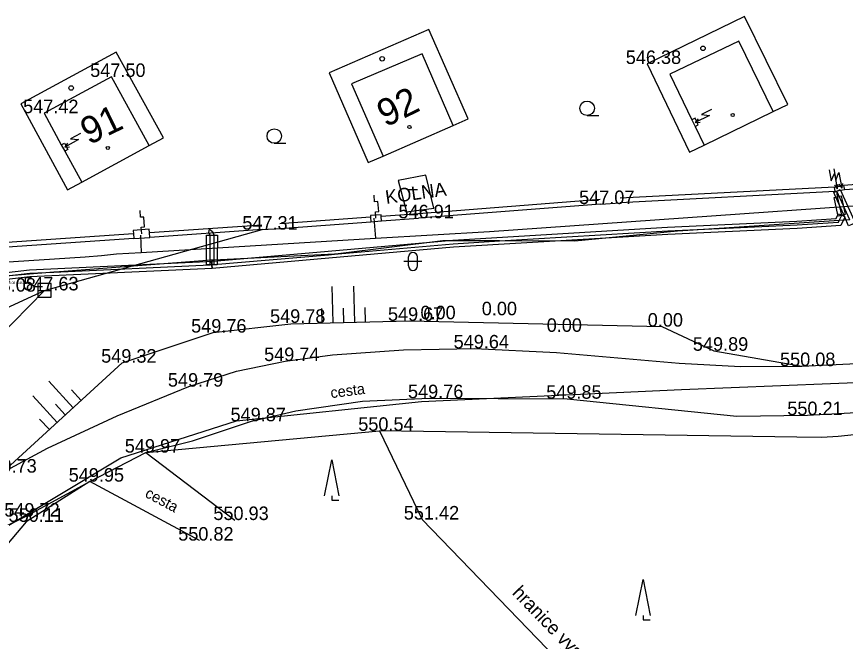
# Model space of a CAD drawing. Extents: x -669995 to -669686, y -1125551 to -1125263.
# Drawn here: x -669816.2 to -669770.25, y -1125420.77 to -1125386.11 of the extents above; entities that cross this region are included whole.
import ezdxf

# ---------------------------------------------------------------- set-up
doc = ezdxf.new("R2010")
doc.units = 0
for name, color, linetype in [('G_Bod_tecka', 7, 'Continuous'), ('G_Bod_vyska', 7, 'Continuous'), ('G_Breh_Teren', 7, 'Continuous'), ('G_Budovy-znacky', 7, 'Continuous'), ('G_Budovy_Objekty', 7, 'Continuous'), ('G_Cesty_Schody', 7, 'Continuous'), ('G_Cisla_orientacni', 7, 'Continuous'), ('G_Ploty', 7, 'Continuous'), ('G_Ploty_vstupy', 7, 'Continuous'), ('G_Popisy_objektu', 7, 'Continuous'), ('G_Popisy_povrchu', 7, 'Continuous'), ('G_Poznamky_odkaz', 7, 'Continuous'), ('G_Site-kanalizace', 7, 'Continuous'), ('G_Site-Rozvadece', 7, 'Continuous'), ('G_Vyskove_srafy', 7, 'Continuous'), ('G_Z_CHRANICKA-TEPLOVOD_kotovane', 7, 'Continuous'), ('G_Z_ELsilove_podz_kotovane', 7, 'Continuous'), ('G_Z_ELsilove_zrusene', 7, 'Continuous'), ('G_Z_PLYNY_podz_geodeticky', 7, 'Continuous'), ('G_Zelen-okraj', 7, 'Continuous'), ('G_Zelen-Znacky', 7, 'Continuous'), ('Vrstva 2', 7, 'Continuous')]:
    doc.layers.add(name, color=color, linetype=linetype)

msp = doc.modelspace()

# ---------------------------------------------------------------- linework, layer by layer
at = {"layer": 'G_Bod_tecka'}
for p, q in [((-669781.25, -1125388.74), (-669781.25, -1125388.74)), ((-669810.93, -1125389.46), (-669810.93, -1125389.46)), ((-669814.67, -1125391.47), (-669814.67, -1125391.47)), ((-669783.83, -1125396.51), (-669783.83, -1125396.51)), ((-669793.91, -1125397.3), (-669793.91, -1125397.3)), ((-669802.58, -1125397.93), (-669802.58, -1125397.93)), ((-669814.65, -1125401.3), (-669814.65, -1125401.3)), ((-669789.63, -1125402.68), (-669789.63, -1125402.68)), ((-669800.99, -1125403.1), (-669800.99, -1125403.1)), ((-669794.43, -1125402.99), (-669794.43, -1125402.99)), ((-669793.03, -1125402.9), (-669793.03, -1125402.9)), ((-669805.34, -1125403.64), (-669805.34, -1125403.64)), ((-669786.03, -1125403.6), (-669786.03, -1125403.6)), ((-669780.43, -1125403.31), (-669780.43, -1125403.31)), ((-669790.8, -1125404.52), (-669790.8, -1125404.52)), ((-669777.54, -1125404.65), (-669777.54, -1125404.65)), ((-669810.34, -1125405.31), (-669810.34, -1125405.31)), ((-669801.31, -1125405.22), (-669801.31, -1125405.22)), ((-669772.67, -1125405.5), (-669772.67, -1125405.5)), ((-669806.64, -1125406.64), (-669806.64, -1125406.64)), ((-669793.32, -1125407.28), (-669793.32, -1125407.28)), ((-669785.67, -1125407.31), (-669785.67, -1125407.31)), ((-669772.35, -1125408.22), (-669772.35, -1125408.22)), ((-669803.17, -1125408.56), (-669803.17, -1125408.56)), ((-669796.07, -1125409.09), (-669796.07, -1125409.09)), ((-669809.03, -1125410.3), (-669809.03, -1125410.3)), ((-669812.14, -1125411.91), (-669812.14, -1125411.91)), ((-669815.71, -1125413.85), (-669815.71, -1125413.85)), ((-669815.66, -1125414.14), (-669815.66, -1125414.14)), ((-669804.1, -1125414.04), (-669804.1, -1125414.04)), ((-669793.71, -1125414.01), (-669793.71, -1125414.01)), ((-669806.05, -1125415.18), (-669806.05, -1125415.18))]:
    msp.add_line(p, q, dxfattribs=at)
at = {"layer": 'G_Breh_Teren'}
for p, q in [((-669814.65, -1125401.3), (-669802.58, -1125397.93)), ((-669814.65, -1125401.3), (-669821.82, -1125408.62)), ((-669805.29, -1125403.64), (-669800.99, -1125403.15)), ((-669800.99, -1125403.15), (-669794.43, -1125402.99)), ((-669794.43, -1125402.99), (-669780.43, -1125403.31)), ((-669810.34, -1125405.31), (-669805.29, -1125403.64)), ((-669816.98, -1125411.41), (-669810.34, -1125405.31)), ((-669809.03, -1125410.3), (-669796.07, -1125409.09)), ((-669812.14, -1125411.91), (-669815.66, -1125414.14)), ((-669815.66, -1125414.14), (-669820.77, -1125420.13))]:
    msp.add_line(p, q, dxfattribs=at)
for points in [[(-669780.43, -1125403.31), (-669777.54, -1125404.65), (-669772.67, -1125405.5)], [(-669769.42, -1125409.28), (-669770.65, -1125409.41), (-669771.56, -1125409.46), (-669772.94, -1125409.45), (-669796.07, -1125409.09)]]:
    msp.add_lwpolyline(points, dxfattribs=at)
at = {"layer": 'G_Budovy-znacky'}
msp.add_line((-669794.47, -1125395.71), (-669793.97, -1125395.71), dxfattribs=at)
for centre, radius in [((-669778.15, -1125387.87), 0.125), ((-669795.93, -1125388.45), 0.125), ((-669813.17, -1125390.07), 0.125), ((-669776.499, -1125391.57), 0.0875), ((-669794.42, -1125392.24), 0.0875), ((-669811.14, -1125393.399), 0.0875)]:
    msp.add_circle(centre, radius, dxfattribs=at)
at = {"layer": 'G_Budovy_Objekty'}
for p, q in [((-669775.84, -1125386.11), (-669781.25, -1125388.74)), ((-669773.45, -1125390.98), (-669775.84, -1125386.11)), ((-669793.35, -1125386.82), (-669798.87, -1125389.24)), ((-669791.16, -1125391.79), (-669793.35, -1125386.82)), ((-669776.16, -1125387.48), (-669779.99, -1125389.3)), ((-669774.26, -1125391.38), (-669776.16, -1125387.48)), ((-669810.68, -1125388.08), (-669815.96, -1125390.96)), ((-669808.06, -1125392.83), (-669810.68, -1125388.08)), ((-669793.72, -1125388.18), (-669797.63, -1125389.85)), ((-669791.99, -1125392.15), (-669793.72, -1125388.18)), ((-669781.25, -1125388.74), (-669778.89, -1125393.63)), ((-669810.93, -1125389.46), (-669814.67, -1125391.47)), ((-669808.85, -1125393.26), (-669810.93, -1125389.46)), ((-669798.87, -1125389.24), (-669796.71, -1125394.21)), ((-669779.99, -1125389.3), (-669778.76, -1125391.84)), ((-669797.63, -1125389.85), (-669795.88, -1125393.85)), ((-669815.96, -1125390.96), (-669813.37, -1125395.73)), ((-669774.26, -1125391.38), (-669773.45, -1125390.98)), ((-669814.67, -1125391.47), (-669813.72, -1125393.22)), ((-669778.08, -1125393.24), (-669774.26, -1125391.38)), ((-669795.88, -1125393.85), (-669791.99, -1125392.15)), ((-669791.99, -1125392.15), (-669791.16, -1125391.79)), ((-669778.76, -1125391.84), (-669778.59, -1125392.2)), ((-669778.59, -1125392.2), (-669778.08, -1125393.24)), ((-669808.85, -1125393.26), (-669808.06, -1125392.83)), ((-669813.72, -1125393.22), (-669813.52, -1125393.58)), ((-669813.52, -1125393.58), (-669812.58, -1125395.3)), ((-669812.58, -1125395.3), (-669808.85, -1125393.26)), ((-669778.89, -1125393.63), (-669778.08, -1125393.24)), ((-669796.71, -1125394.21), (-669795.88, -1125393.85)), ((-669793.51, -1125394.91), (-669795.04, -1125395.21)), ((-669793.07, -1125396.73), (-669793.51, -1125394.91)), ((-669813.37, -1125395.73), (-669812.58, -1125395.3)), ((-669795.04, -1125395.21), (-669794.58, -1125396.94)), ((-669794.58, -1125396.94), (-669793.07, -1125396.73))]:
    msp.add_line(p, q, dxfattribs=at)
at = {"layer": 'G_Cesty_Schody'}
for p, q in [((-669809.03, -1125410.3), (-669804.1, -1125414.04)), ((-669806.05, -1125415.18), (-669812.14, -1125411.91))]:
    msp.add_line(p, q, dxfattribs=at)
for points in [[(-669831.37, -1125419.84), (-669824.18, -1125415.63), (-669816.98, -1125411.41), (-669814.49, -1125410.06), (-669810.62, -1125408.26), (-669806.64, -1125406.64), (-669804.01, -1125405.78), (-669801.31, -1125405.22), (-669798.68, -1125404.88), (-669794.74, -1125404.59), (-669790.8, -1125404.52), (-669786.26, -1125404.75), (-669779.47, -1125405.34), (-669776.07, -1125405.53), (-669772.67, -1125405.5), (-669762.05, -1125404.98), (-669751.43, -1125404.46)], [(-669827.31, -1125430.89), (-669827.81, -1125427.44), (-669828.32, -1125424), (-669828.27, -1125423.02), (-669828.02, -1125422.32), (-669827.38, -1125421.32), (-669826.53, -1125420.43), (-669825.24, -1125419.34), (-669822.95, -1125417.69), (-669821.19, -1125416.63), (-669818.5, -1125415.21), (-669815.71, -1125413.85), (-669812.14, -1125411.91), (-669809.03, -1125410.3), (-669806.44, -1125409.64), (-669803.17, -1125408.56), (-669800.72, -1125407.98), (-669797.03, -1125407.45), (-669793.32, -1125407.28), (-669785.67, -1125407.31), (-669776.28, -1125408.27), (-669772.35, -1125408.22), (-669761.86, -1125407.64), (-669751.66, -1125407.06)]]:
    msp.add_lwpolyline(points, dxfattribs=at)
at = {"layer": 'G_Ploty'}
for p, q in [((-669758.46, -1125394.59), (-669770.35, -1125395.48)), ((-669758.44, -1125394.84), (-669770.31, -1125395.73)), ((-669770.86, -1125395.57), (-669782.74, -1125396.19)), ((-669770.82, -1125395.82), (-669782.73, -1125396.44)), ((-669783.85, -1125396.26), (-669793.92, -1125397.05)), ((-669783.83, -1125396.51), (-669793.91, -1125397.3)), ((-669796.58, -1125397.24), (-669801.6, -1125397.61)), ((-669793.92, -1125397.05), (-669795.98, -1125397.2)), ((-669802.6, -1125397.68), (-669808.82, -1125398.11)), ((-669801.58, -1125397.86), (-669796.56, -1125397.49)), ((-669795.96, -1125397.44), (-669793.91, -1125397.3)), ((-669809.72, -1125398.17), (-669819.84, -1125398.86)), ((-669802.58, -1125397.93), (-669808.81, -1125398.36)), ((-669809.7, -1125398.42), (-669819.82, -1125399.11))]:
    msp.add_line(p, q, dxfattribs=at)
at = {"layer": 'G_Ploty_vstupy'}
for p, q in [((-669783.83, -1125396.51), (-669782.73, -1125396.44)), ((-669802.58, -1125397.93), (-669801.58, -1125397.86))]:
    msp.add_line(p, q, dxfattribs=at)
at = {"layer": 'G_Site-kanalizace'}
msp.add_line((-669815.025, -1125401.3), (-669814.275, -1125401.3), dxfattribs=at)
msp.add_lwpolyline([(-669815.025, -1125401.674), (-669814.275, -1125401.674), (-669814.275, -1125400.924), (-669815.025, -1125400.924)], close=True, dxfattribs=at)
at = {"layer": 'G_Site-Rozvadece'}
for p, q in [((-669777.676, -1125391.264), (-669778.239, -1125391.537)), ((-669778.58, -1125391.75), (-669778.76, -1125391.84)), ((-669777.793, -1125391.598), (-669778.58, -1125391.98)), ((-669778.41, -1125392.11), (-669778.58, -1125391.75)), ((-669778.239, -1125391.537), (-669777.793, -1125391.598)), ((-669778.59, -1125392.2), (-669778.41, -1125392.11)), ((-669778.407, -1125391.774), (-669778.58, -1125391.98)), ((-669778.58, -1125391.98), (-669778.311, -1125391.972)), ((-669812.661, -1125392.592), (-669813.211, -1125392.892)), ((-669813.72, -1125393.22), (-669813.54, -1125393.13)), ((-669813.54, -1125393.13), (-669813.35, -1125393.48)), ((-669812.761, -1125392.932), (-669813.529, -1125393.35)), ((-669813.367, -1125393.137), (-669813.529, -1125393.35)), ((-669813.211, -1125392.892), (-669812.761, -1125392.932)), ((-669813.529, -1125393.35), (-669813.261, -1125393.33)), ((-669813.35, -1125393.48), (-669813.52, -1125393.58)), ((-669771.152, -1125394.605), (-669771.043, -1125395.221)), ((-669771.043, -1125395.221), (-669770.862, -1125394.809)), ((-669770.902, -1125394.565), (-669770.793, -1125395.181)), ((-669770.862, -1125394.809), (-669770.71, -1125395.67)), ((-669770.793, -1125395.181), (-669770.612, -1125394.769)), ((-669770.612, -1125394.769), (-669770.46, -1125395.63)), ((-669770.71, -1125395.67), (-669770.644, -1125395.41)), ((-669770.611, -1125395.408), (-669770.46, -1125395.63)), ((-669770.46, -1125395.63), (-669770.394, -1125395.37)), ((-669770.861, -1125395.448), (-669770.71, -1125395.67))]:
    msp.add_line(p, q, dxfattribs=at)
for points in [[(-669770.82, -1125395.82), (-669770.86, -1125395.57), (-669770.35, -1125395.48), (-669770.31, -1125395.73)], [(-669796.58, -1125397.14), (-669796.58, -1125397.24), (-669796.56, -1125397.49), (-669795.96, -1125397.44), (-669795.98, -1125397.2), (-669795.98, -1125397.1)], [(-669809.74, -1125397.97), (-669809.72, -1125398.17), (-669809.7, -1125398.42), (-669808.81, -1125398.36), (-669808.82, -1125398.11), (-669808.84, -1125397.91)]]:
    msp.add_lwpolyline(points, close=True, dxfattribs=at)
for points in [[(-669796.28, -1125397.3), (-669796.306, -1125396.933), (-669796.124, -1125396.919), (-669796.164, -1125396.369), (-669796.347, -1125396.381), (-669796.375, -1125396.014)], [(-669809.26, -1125398.16), (-669809.284, -1125397.793), (-669809.102, -1125397.78), (-669809.139, -1125397.229), (-669809.322, -1125397.241), (-669809.348, -1125396.874)]]:
    msp.add_lwpolyline(points, dxfattribs=at)
at = {"layer": 'G_Vyskove_srafy'}
for p, q in [((-669798.65, -1125403.09), (-669798.7, -1125401.09)), ((-669797.45, -1125403.06), (-669797.5, -1125401.06)), ((-669799.25, -1125403.11), (-669799.27, -1125402.31)), ((-669798.05, -1125403.08), (-669798.07, -1125402.28)), ((-669796.85, -1125403.05), (-669796.87, -1125402.25)), ((-669813.06, -1125407.81), (-669814.41, -1125406.33)), ((-669812.62, -1125407.4), (-669813.16, -1125406.81)), ((-669813.94, -1125408.62), (-669815.3, -1125407.15)), ((-669813.5, -1125408.21), (-669814.04, -1125407.62)), ((-669814.38, -1125409.02), (-669814.93, -1125408.44))]:
    msp.add_line(p, q, dxfattribs=at)
at = {"layer": 'G_Z_CHRANICKA-TEPLOVOD_kotovane'}
for points in [[(-669770.538, -1125395.708), (-669769.765, -1125397.43), (-669769.708, -1125397.558), (-669769.89, -1125397.64), (-669770.073, -1125397.722), (-669770.29, -1125397.238), (-669770.305, -1125397.203), (-669770.349, -1125397.105), (-669770.79, -1125396.122), (-669770.903, -1125395.872)], [(-669770.495, -1125396.056), (-669770.265, -1125397.086), (-669770.349, -1125397.105), (-669770.46, -1125397.13), (-669770.655, -1125397.174), (-669770.67, -1125397.106), (-669770.885, -1125396.144), (-669770.79, -1125396.122)], [(-669770.67, -1125397.106), (-669770.641, -1125397.044), (-669770.46, -1125397.13), (-669770.305, -1125397.203), (-669770.279, -1125397.216), (-669770.29, -1125397.238), (-669770.51, -1125397.702), (-669772.919, -1125397.86), (-669780.089, -1125398.2), (-669791.975, -1125398.909), (-669798.883, -1125399.519), (-669805.353, -1125400.079), (-669805.37, -1125399.88), (-669805.387, -1125399.681), (-669805.384, -1125399.68), (-669805.069, -1125399.653), (-669798.917, -1125399.121), (-669792.005, -1125398.51), (-669780.111, -1125397.8), (-669772.941, -1125397.46), (-669770.77, -1125397.318)], [(-669805.669, -1125399.694), (-669805.66, -1125398.238), (-669805.06, -1125398.242), (-669805.069, -1125399.653), (-669805.07, -1125399.882), (-669805.37, -1125399.88), (-669805.67, -1125399.878)], [(-669805.384, -1125399.68), (-669805.379, -1125399.68), (-669805.37, -1125399.88), (-669805.361, -1125400.08), (-669815.454, -1125400.55), (-669822.336, -1125401.35), (-669822.475, -1125400.723), (-669822.28, -1125400.68), (-669822.085, -1125400.637), (-669822.083, -1125400.645), (-669822.024, -1125400.91), (-669815.486, -1125400.151), (-669805.669, -1125399.694)]]:
    msp.add_lwpolyline(points, close=True, dxfattribs=at)
at = {"layer": 'G_Z_ELsilove_podz_kotovane'}
for points in [[(-669817.058, -1125400.535), (-669815.47, -1125400.35), (-669814.133, -1125400.288), (-669805.47, -1125399.885), (-669805.468, -1125399.626), (-669805.46, -1125398.26), (-669805.534, -1125398.085), (-669805.5, -1125397.91), (-669805.342, -1125398.028), (-669805.26, -1125398.22), (-669805.268, -1125399.617), (-669805.27, -1125399.871), (-669798.9, -1125399.32), (-669798.567, -1125399.291), (-669798.373, -1125399.273), (-669791.99, -1125398.71), (-669789.434, -1125398.557), (-669780.1, -1125398), (-669777.253, -1125397.865), (-669772.93, -1125397.66), (-669770.64, -1125397.51), (-669770.599, -1125397.423), (-669770.46, -1125397.13), (-669770.69, -1125396.1), (-669770.72, -1125395.79)], [(-669770.005, -1125397.384), (-669770.72, -1125395.79)], [(-669825.82, -1125421.69), (-669825.4, -1125420.37), (-669823.47, -1125418.72), (-669817.66, -1125414.93), (-669810.41, -1125410.58), (-669804, -1125408.54), (-669793.75, -1125407.46), (-669779.34, -1125406.79), (-669768.33, -1125406.35), (-669758.83, -1125405.98), (-669749.3, -1125405.76), (-669740.13, -1125406.68), (-669730.37, -1125408.08), (-669716.63, -1125408.89), (-669706.64, -1125409.51), (-669701.451, -1125408.897)]]:
    msp.add_lwpolyline(points, dxfattribs=at)
at = {"layer": 'G_Z_ELsilove_zrusene'}
msp.add_lwpolyline([(-669770.005, -1125397.384), (-669770.599, -1125397.423), (-669777.253, -1125397.865), (-669779.558, -1125398.018), (-669785.243, -1125398.57), (-669789.434, -1125398.557), (-669792.56, -1125398.548), (-669798.373, -1125399.273), (-669798.474, -1125399.286), (-669798.567, -1125399.291), (-669805.268, -1125399.617), (-669805.468, -1125399.626), (-669805.628, -1125399.634), (-669814.064, -1125400.282), (-669814.133, -1125400.288), (-669817.058, -1125400.535)], dxfattribs=at)
msp.add_lwpolyline([(-669770.005, -1125397.384), (-669770.599, -1125397.423), (-669777.253, -1125397.865), (-669779.558, -1125398.018), (-669785.243, -1125398.57), (-669789.434, -1125398.557), (-669792.56, -1125398.548), (-669798.373, -1125399.273), (-669798.474, -1125399.286), (-669798.567, -1125399.291), (-669805.268, -1125399.617), (-669805.468, -1125399.626), (-669805.628, -1125399.634), (-669814.064, -1125400.282), (-669814.133, -1125400.288), (-669817.058, -1125400.535)], dxfattribs=at)
at = {"layer": 'G_Z_PLYNY_podz_geodeticky'}
for points in [[(-669839.96, -1125401.69), (-669839.65, -1125401.68), (-669829.38, -1125401.08), (-669823.72, -1125400.23), (-669823.35, -1125400.2), (-669822.91, -1125400.13), (-669812.4, -1125399.44), (-669811.498, -1125399.357), (-669810.66, -1125399.28), (-669809.29, -1125399.19), (-669796.31, -1125398.41), (-669789.98, -1125398.03), (-669757.52, -1125395.74), (-669752.71, -1125395.41)], [(-669796.4, -1125397.3), (-669796.31, -1125398.41)], [(-669809.33, -1125398.23), (-669809.29, -1125399.19)]]:
    msp.add_lwpolyline(points, dxfattribs=at)
at = {"layer": 'G_Zelen-okraj'}
for p, q in [((-669823.54, -1125405.41), (-669814.65, -1125401.3)), ((-669796.07, -1125409.09), (-669793.71, -1125414.01))]:
    msp.add_line(p, q, dxfattribs=at)
msp.add_lwpolyline([(-669793.71, -1125414.01), (-669776.68, -1125431.65), (-669769.13, -1125449.01), (-669769.97, -1125459.47), (-669765.23, -1125461.27), (-669762.44, -1125465.41)], dxfattribs=at)
at = {"layer": 'G_Zelen-Znacky'}
for p, q in [((-669784.572, -1125391.6), (-669783.922, -1125391.597)), ((-669801.912, -1125393.14), (-669801.262, -1125393.137)), ((-669794.48, -1125399.94), (-669794.48, -1125399.44)), ((-669793.98, -1125399.94), (-669793.98, -1125399.44)), ((-669793.73, -1125399.69), (-669794.73, -1125399.69)), ((-669799.13, -1125412.69), (-669798.73, -1125410.69)), ((-669798.73, -1125410.69), (-669798.33, -1125412.69)), ((-669798.73, -1125412.69), (-669798.73, -1125412.94)), ((-669798.73, -1125412.94), (-669798.33, -1125412.94)), ((-669781.87, -1125419.33), (-669781.47, -1125417.33)), ((-669781.47, -1125417.33), (-669781.07, -1125419.33)), ((-669781.47, -1125419.33), (-669781.47, -1125419.58)), ((-669781.47, -1125419.58), (-669781.07, -1125419.58))]:
    msp.add_line(p, q, dxfattribs=at)
for centre in [(-669784.572, -1125391.197), (-669801.912, -1125392.737)]:
    msp.add_circle(centre, 0.403, dxfattribs=at)
for centre, start, end in [((-669794.23, -1125399.44), 0, 180), ((-669794.23, -1125399.94), 180, 0)]:
    msp.add_arc(centre, 0.25, start, end, dxfattribs=at)

# ---------------------------------------------------------------- texts
at = {"layer": 'G_Bod_vyska'}
for s, p in [('546.38', (-669782.428, -1125388.74)), ('547.50', (-669812.116, -1125389.46)), ('547.42', (-669815.834, -1125391.47)), ('547.07', (-669785.016, -1125396.51)), ('546.91', (-669795.028, -1125397.3)), ('547.31', (-669803.682, -1125397.93)), ('548.08', (-669818.196, -1125401.37)), ('547.63', (-669815.828, -1125401.3)), ('549.67', (-669795.61, -1125402.99)), ('0.00', (-669793.81, -1125402.9)), ('0.00', (-669790.41, -1125402.68)), ('549.78', (-669802.146, -1125403.1)), ('0.00', (-669781.21, -1125403.31)), ('549.76', (-669806.52, -1125403.64)), ('0.00', (-669786.81, -1125403.6)), ('549.64', (-669791.97, -1125404.52)), ('549.89', (-669778.708, -1125404.65)), ('549.32', (-669811.506, -1125405.31)), ('549.74', (-669802.476, -1125405.22)), ('550.08', (-669773.877, -1125405.5)), ('549.79', (-669807.808, -1125406.64)), ('549.76', (-669794.5, -1125407.28)), ('549.85', (-669786.836, -1125407.31)), ('549.87', (-669804.336, -1125408.56)), ('550.21', (-669773.474, -1125408.22)), ('550.54', (-669797.256, -1125409.09)), ('549.97', (-669810.198, -1125410.3)), ('549.73', (-669818.146, -1125411.41)), ('549.95', (-669813.308, -1125411.91)), ('549.72', (-669816.876, -1125413.85)), ('550.93', (-669805.288, -1125414.04)), ('551.42', (-669794.732, -1125414.01)), ('550.11', (-669816.642, -1125414.14)), ('550.82', (-669807.236, -1125415.18))]:
    msp.add_text(s, height=0.75, dxfattribs=at).set_placement(p)
at = {"layer": 'G_Cisla_orientacni'}
for s, p in [('92', (-669795.746, -1125392.271)), ('91', (-669812.184, -1125393.255))]:
    msp.add_text(s, height=1.5, rotation=25.938, dxfattribs=at).set_placement(p)
at = {"layer": 'G_Popisy_objektu'}
msp.add_text('KOLNA', height=0.75, rotation=7.9175, dxfattribs=at).set_placement((-669795.702, -1125396.504))
at = {"layer": 'G_Popisy_povrchu'}
for rotation, p in [(7.4354, (-669798.759, -1125407.282)), (331.7666, (-669809.125, -1125412.729))]:
    msp.add_text('cesta', height=0.6, rotation=rotation, dxfattribs=at).set_placement(p)
at = {"layer": 'G_Poznamky_odkaz'}
msp.add_text('hranice vysokého lesa', height=0.75, rotation=313.992, dxfattribs=at).set_placement((-669788.768, -1125418.119))
at = {"layer": 'Vrstva 2'}
msp.add_text('548.08 (546.34)', height=0.13163, dxfattribs=at).set_placement((-669816.824, -1125400.948))

doc.saveas('drawing.dxf')
